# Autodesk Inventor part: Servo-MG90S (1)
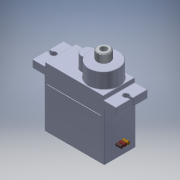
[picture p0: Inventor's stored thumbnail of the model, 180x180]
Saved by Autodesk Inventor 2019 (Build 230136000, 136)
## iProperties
Created: 2017-09
Part Number: Servo-MG90S (1)
Material: Generic
Document SubType Name: Modeling
Designer: TANVI KOTHARKAR
Density: 1 g/cm^3
Appearance: Default
Author: TANVI KOTHARKAR
Sending System: SolidWorks 2017
Last Author: Lynx
Last Saved: 2017-09-26
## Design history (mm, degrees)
feature "Cut-Extrude3"
body "Solid1"
